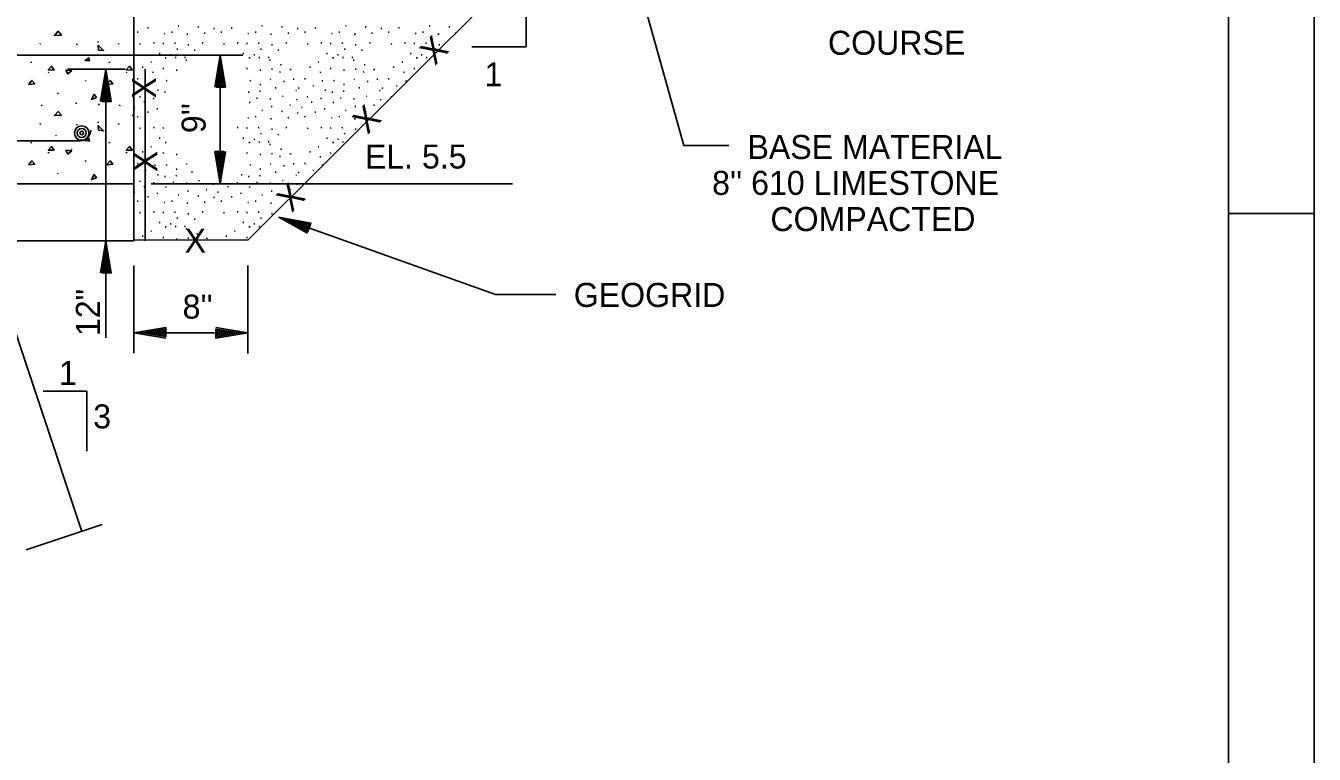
# Model space of a CAD drawing. Extents: x 0 to 320, y -4 to 473.
# Drawn here: x 32.48 to 40, y 10.85 to 15.09 of the extents above; entities that cross this region are included whole.
import ezdxf

# ---------------------------------------------------------------- set-up
doc = ezdxf.new("R2010")
doc.units = 0
for name, color, linetype in [('Level 1', 7, 'Continuous'), ('Level 10', 7, 'Continuous'), ('Level 2', 7, 'Continuous'), ('Level 25', 7, 'Continuous'), ('Level 3', 7, 'Continuous'), ('Level 44', 7, 'Continuous'), ('Level 50', 7, 'Continuous')]:
    doc.layers.add(name, color=color, linetype=linetype)

msp = doc.modelspace()

# ---------------------------------------------------------------- linework, layer by layer
at = {"layer": 'Level 1'}
msp.add_line((39.5, 14), (40, 14), dxfattribs=at)
for points in [[(0, 28), (40, 28), (40, 0), (0, 0)], [(1.5, 27.5), (39.5, 27.5), (39.5, 0.5), (1.5, 0.5)]]:
    msp.add_lwpolyline(points, close=True, dxfattribs=at)
at = {"layer": 'Level 10'}
for p, q in [((32.5694, 14.9868), (32.5711, 14.9913)), ((32.7824, 14.9825), (32.7824, 14.9888)), ((32.9077, 14.996), (32.9077, 15.0018)), ((33.0249, 14.9868), (33.0267, 14.9913)), ((32.5169, 14.8781), (32.5159, 14.8841)), ((32.6614, 14.92), (32.6592, 14.9249)), ((32.9724, 14.8781), (32.9714, 14.8841)), ((32.6184, 14.8192), (32.6153, 14.8244)), ((32.7514, 14.84), (32.751, 14.8446)), ((33.0739, 14.8192), (33.0708, 14.8244)), ((32.833, 14.7704), (32.8358, 14.776)), ((32.6726, 14.6978), (32.673, 14.7029)), ((32.5756, 14.627), (32.5774, 14.6333)), ((32.7785, 14.6394), (32.7777, 14.6441)), ((32.9099, 14.632), (32.9099, 14.6383)), ((33.0311, 14.627), (33.0329, 14.6333)), ((32.5694, 14.5192), (32.5711, 14.5237)), ((32.7824, 14.5149), (32.7824, 14.5212)), ((32.9077, 14.5284), (32.9077, 14.5342)), ((33.0249, 14.5192), (33.0267, 14.5237)), ((32.6614, 14.4524), (32.6592, 14.4573)), ((32.5169, 14.4104), (32.5159, 14.4165)), ((32.6184, 14.3516), (32.6153, 14.3568)), ((32.7514, 14.3724), (32.751, 14.377)), ((32.9724, 14.4104), (32.9714, 14.4165)), ((33.0739, 14.3516), (33.0708, 14.3568)), ((32.833, 14.3028), (32.8358, 14.3084)), ((32.6726, 14.2302), (32.673, 14.2353)), ((32.778, 14.1747), (32.7777, 14.1765))]:
    msp.add_line(p, q, dxfattribs=at)
for points in [[(32.693, 15.0403), (32.6732, 15.0618), (32.652, 15.0381)], [(32.9093, 14.9525), (32.9077, 14.9803), (32.9385, 14.9502)], [(32.8564, 14.889), (32.8311, 14.8922), (32.8524, 14.9065)], [(32.6511, 14.8357), (32.6344, 14.8578), (32.6155, 14.8365)], [(32.753, 14.8333), (32.7308, 14.8135), (32.7189, 14.8357)], [(33.1067, 14.8357), (33.0899, 14.8578), (33.071, 14.8365)], [(32.5003, 14.7517), (32.5209, 14.7754), (32.5375, 14.7558)], [(32.9558, 14.7517), (32.9764, 14.7754), (32.993, 14.7558)], [(32.8963, 14.6758), (32.8679, 14.6647), (32.8829, 14.6954)], [(32.693, 14.5727), (32.6732, 14.5942), (32.652, 14.5704)], [(32.9093, 14.4849), (32.9077, 14.5127), (32.9385, 14.4826)], [(32.8564, 14.4214), (32.8311, 14.4246), (32.8524, 14.4389)], [(32.6511, 14.3681), (32.6344, 14.3902), (32.6155, 14.3689)], [(32.753, 14.3657), (32.7308, 14.3459), (32.7189, 14.3681)], [(33.1067, 14.3681), (33.0899, 14.3902), (33.071, 14.3689)], [(32.5003, 14.2841), (32.5209, 14.3078), (32.5375, 14.2882)], [(32.9558, 14.2841), (32.9764, 14.3078), (32.993, 14.2882)], [(32.8963, 14.2082), (32.8679, 14.1971), (32.8829, 14.2278)]]:
    msp.add_lwpolyline(points, close=True, dxfattribs=at)
msp.add_lwpolyline([(33.1107, 14.5741), (33.1075, 14.5704), (33.1108, 14.5706)], dxfattribs=at)
at = {"layer": 'Level 2'}
for p, q in [((33.1141, 13.8403), (33.1141, 16.1319)), ((32.7275, 14.8403), (33.0645, 14.8403)), ((33.1816, 13.8403), (33.1816, 14.8403)), ((23.4266, 14.4236), (32.8016, 14.4236)), ((33.1141, 14.1736), (28.5308, 14.1736)), ((33.1141, 13.8403), (28.5308, 13.8403))]:
    msp.add_line(p, q, dxfattribs=at)
at = {"layer": 'Level 25'}
for p, q in [((32.8113, 12.1472), (32.2469, 13.8403)), ((32.9308, 12.1871), (32.4863, 12.0389))]:
    msp.add_line(p, q, dxfattribs=at)
at = {"layer": 'Level 3'}
for p, q in [((33.7808, 13.8444), (35.7413, 15.7986)), ((35.4028, 14.9715), (35.4028, 15.321)), ((33.1397, 15.0568), (33.1342, 15.0563)), ((33.2003, 15.0824), (33.1948, 15.0821)), ((33.2964, 15.0487), (33.2913, 15.0496)), ((33.3397, 15.0568), (33.3342, 15.0563)), ((33.3782, 15.0934), (33.3727, 15.0931)), ((33.4308, 15.0446), (33.4241, 15.0446)), ((33.4938, 15.0879), (33.4883, 15.0876)), ((33.5306, 15.0513), (33.5249, 15.0508)), ((33.5847, 15.0779), (33.5798, 15.0784)), ((33.6278, 15.0568), (33.6223, 15.0563)), ((33.6884, 15.0824), (33.6829, 15.0821)), ((33.7846, 15.0487), (33.7794, 15.0496)), ((33.8278, 15.0568), (33.8223, 15.0563)), ((33.8663, 15.0934), (33.8608, 15.0931)), ((33.9189, 15.0446), (33.9122, 15.0446)), ((33.9819, 15.0879), (33.9764, 15.0876)), ((34.0187, 15.0513), (34.0131, 15.0508)), ((34.0728, 15.0779), (34.0679, 15.0784)), ((34.1159, 15.0568), (34.1104, 15.0563)), ((34.1766, 15.0824), (34.1711, 15.0821)), ((34.2727, 15.0487), (34.2676, 15.0496)), ((34.3159, 15.0568), (34.3104, 15.0563)), ((34.3544, 15.0934), (34.3489, 15.0931)), ((34.4071, 15.0446), (34.4003, 15.0446)), ((34.4701, 15.0879), (34.4646, 15.0876)), ((34.5068, 15.0513), (34.5012, 15.0508)), ((34.5609, 15.0779), (34.5561, 15.0784)), ((34.6041, 15.0568), (34.5986, 15.0563)), ((34.6647, 15.0824), (34.6592, 15.0821)), ((34.7608, 15.0487), (34.7557, 15.0496)), ((34.8041, 15.0568), (34.7986, 15.0563)), ((34.8426, 15.0934), (34.8371, 15.0931)), ((34.8952, 15.0446), (34.8884, 15.0446)), ((34.9582, 15.0879), (34.9527, 15.0876)), ((34.9912, 15.051), (34.9893, 15.0508)), ((33.1548, 14.9898), (33.1489, 14.9868)), ((33.2351, 14.9943), (33.2296, 14.9939)), ((33.2902, 14.9907), (33.2847, 14.9902)), ((33.3581, 14.9926), (33.3526, 14.9921)), ((33.3708, 14.9577), (33.3653, 14.9572)), ((33.4351, 14.9833), (33.4296, 14.9829)), ((33.5194, 14.9943), (33.5139, 14.9939)), ((33.6429, 14.9898), (33.6371, 14.9868)), ((33.7232, 14.9943), (33.7177, 14.9939)), ((33.7783, 14.9907), (33.7728, 14.9902)), ((33.8462, 14.9926), (33.8407, 14.9921)), ((33.8589, 14.9577), (33.8534, 14.9572)), ((33.9232, 14.9833), (33.9177, 14.9829)), ((34.0076, 14.9943), (34.0021, 14.9939)), ((34.1311, 14.9898), (34.1252, 14.9868)), ((34.2113, 14.9943), (34.2058, 14.9939)), ((34.2664, 14.9907), (34.2609, 14.9902)), ((34.3343, 14.9926), (34.3288, 14.9921)), ((34.3471, 14.9577), (34.3416, 14.9572)), ((34.4113, 14.9833), (34.4058, 14.9829)), ((34.4957, 14.9943), (34.4902, 14.9939)), ((34.6192, 14.9898), (34.6133, 14.9868)), ((34.6994, 14.9943), (34.6939, 14.9939)), ((34.7546, 14.9907), (34.7491, 14.9902)), ((34.8224, 14.9926), (34.8169, 14.9921)), ((34.8352, 14.9577), (34.8297, 14.9572)), ((34.8994, 14.9833), (34.8939, 14.9829)), ((35.0857, 14.9715), (35.4028, 14.9715)), ((33.7501, 14.9236), (32.2673, 14.9236)), ((33.2187, 14.8818), (33.2132, 14.8813)), ((33.2682, 14.9321), (33.2627, 14.9316)), ((33.3044, 14.9064), (33.2977, 14.9064)), ((33.3324, 14.9246), (33.3269, 14.9242)), ((33.3618, 14.9092), (33.3562, 14.9088)), ((33.4163, 14.9092), (33.4101, 14.9092)), ((33.4241, 14.8946), (33.4186, 14.8942)), ((33.4718, 14.9522), (33.4663, 14.9517)), ((33.6186, 14.1736), (33.6186, 14.9236)), ((33.7563, 14.9321), (33.7508, 14.9316)), ((33.7926, 14.9064), (33.7858, 14.9064)), ((33.8206, 14.9246), (33.8151, 14.9242)), ((33.8499, 14.9092), (33.8443, 14.9088)), ((33.9044, 14.9092), (33.8982, 14.9092)), ((33.9122, 14.8946), (33.9067, 14.8942)), ((33.9599, 14.9522), (33.9544, 14.9517)), ((34.1949, 14.8818), (34.1894, 14.8813)), ((34.2444, 14.9321), (34.2389, 14.9316)), ((34.2807, 14.9064), (34.2739, 14.9064)), ((34.3087, 14.9246), (34.3032, 14.9242)), ((34.3381, 14.9092), (34.3324, 14.9088)), ((34.3926, 14.9092), (34.3863, 14.9092)), ((34.4003, 14.8946), (34.3948, 14.8942)), ((34.4481, 14.9522), (34.4426, 14.9517)), ((34.6831, 14.8818), (34.6776, 14.8813)), ((34.7326, 14.9321), (34.7271, 14.9316)), ((34.7688, 14.9064), (34.7621, 14.9064)), ((34.7968, 14.9246), (34.7913, 14.9242)), ((34.8262, 14.9092), (34.8206, 14.9088)), ((33.1691, 14.8524), (33.1636, 14.8519)), ((33.2296, 14.8231), (33.2241, 14.8226)), ((33.2902, 14.8451), (33.2847, 14.8447)), ((33.3673, 14.8359), (33.3618, 14.8354)), ((33.7783, 14.8451), (33.7728, 14.8447)), ((33.8554, 14.8359), (33.8499, 14.8354)), ((33.9232, 14.8414), (33.9177, 14.8409)), ((33.9709, 14.8248), (33.9654, 14.8244)), ((33.9764, 14.8671), (33.9709, 14.8666)), ((34.0318, 14.8389), (34.0253, 14.8399)), ((34.1453, 14.8524), (34.1398, 14.8519)), ((34.2058, 14.8231), (34.2003, 14.8226)), ((34.2664, 14.8451), (34.2609, 14.8447)), ((34.3436, 14.8359), (34.3381, 14.8354)), ((34.4113, 14.8414), (34.4058, 14.8409)), ((34.4591, 14.8248), (34.4536, 14.8244)), ((34.4646, 14.8671), (34.4591, 14.8666)), ((34.5199, 14.8389), (34.5134, 14.8399)), ((34.6334, 14.8524), (34.6279, 14.8519)), ((34.6939, 14.8231), (34.6884, 14.8226)), ((34.7546, 14.8451), (34.7491, 14.8447)), ((33.1397, 14.7844), (33.1342, 14.7841)), ((33.1874, 14.7442), (33.1818, 14.7438)), ((33.2406, 14.7736), (33.2351, 14.7731)), ((33.3098, 14.7754), (33.3031, 14.7736)), ((33.7979, 14.7754), (33.7912, 14.7736)), ((33.8554, 14.7516), (33.8499, 14.7511)), ((33.9143, 14.7822), (33.9096, 14.7803)), ((33.9453, 14.7332), (33.9398, 14.7327)), ((33.9929, 14.7698), (33.9874, 14.7694)), ((34.0498, 14.7827), (34.0443, 14.7822)), ((34.0784, 14.7292), (34.0728, 14.7326)), ((34.1159, 14.7844), (34.1104, 14.7841)), ((34.1637, 14.7442), (34.1581, 14.7438)), ((34.2168, 14.7736), (34.2113, 14.7731)), ((34.2861, 14.7754), (34.2793, 14.7736)), ((34.3436, 14.7516), (34.3381, 14.7511)), ((34.4024, 14.7822), (34.3977, 14.7803)), ((34.4334, 14.7332), (34.4279, 14.7327)), ((34.4811, 14.7698), (34.4756, 14.7694)), ((34.5379, 14.7827), (34.5324, 14.7822)), ((34.5666, 14.7292), (34.5609, 14.7326)), ((34.6041, 14.7844), (34.5986, 14.7841)), ((34.6518, 14.7442), (34.6462, 14.7438)), ((34.7049, 14.7736), (34.6994, 14.7731)), ((33.1544, 14.6799), (33.1489, 14.6796)), ((33.2333, 14.6707), (33.2278, 14.6703)), ((33.2589, 14.7184), (33.2534, 14.7179)), ((33.2993, 14.7076), (33.2938, 14.7071)), ((33.7874, 14.7076), (33.7819, 14.7071)), ((33.8369, 14.6727), (33.8314, 14.6722)), ((33.8534, 14.7129), (33.8479, 14.7124)), ((33.9141, 14.6689), (33.9084, 14.6684)), ((33.9864, 14.6828), (33.9812, 14.6853)), ((34.0646, 14.7167), (34.0591, 14.7162)), ((34.0701, 14.6634), (34.0646, 14.6629)), ((34.1307, 14.6799), (34.1252, 14.6796)), ((34.2096, 14.6707), (34.2041, 14.6703)), ((34.2352, 14.7184), (34.2297, 14.7179)), ((34.2756, 14.7076), (34.2701, 14.7071)), ((34.3251, 14.6727), (34.3196, 14.6722)), ((34.3416, 14.7129), (34.3361, 14.7124)), ((34.4022, 14.6689), (34.3966, 14.6684)), ((34.4746, 14.6828), (34.4693, 14.6853)), ((34.5527, 14.7167), (34.5472, 14.7162)), ((34.5582, 14.6634), (34.5527, 14.6629)), ((34.6188, 14.6799), (34.6133, 14.6796)), ((33.1213, 14.6176), (33.1158, 14.6171)), ((33.1783, 14.6488), (33.1728, 14.6483)), ((33.2003, 14.5901), (33.1948, 14.5897)), ((33.2553, 14.6102), (33.2498, 14.6098)), ((33.7929, 14.6469), (33.7874, 14.6464)), ((33.8663, 14.6011), (33.8608, 14.6007)), ((33.9214, 14.6231), (33.9159, 14.6226)), ((33.9819, 14.5956), (33.9764, 14.5952)), ((34.0297, 14.6323), (34.0242, 14.6318)), ((34.0728, 14.5856), (34.0679, 14.5861)), ((34.0976, 14.6176), (34.0921, 14.6171)), ((34.1546, 14.6488), (34.1491, 14.6483)), ((34.1766, 14.5901), (34.1711, 14.5897)), ((34.2316, 14.6102), (34.2261, 14.6098)), ((34.2811, 14.6469), (34.2756, 14.6464)), ((34.3544, 14.6011), (34.3489, 14.6007)), ((34.4096, 14.6231), (34.4041, 14.6226)), ((34.4701, 14.5956), (34.4646, 14.5952)), ((34.5178, 14.6323), (34.5123, 14.6318)), ((33.1397, 14.5644), (33.1342, 14.5639)), ((33.4308, 14.5522), (33.4241, 14.5522)), ((33.7846, 14.5563), (33.7794, 14.5572)), ((33.8278, 14.5644), (33.8223, 14.5639)), ((33.9189, 14.5522), (33.9122, 14.5522)), ((34.0187, 14.5589), (34.0131, 14.5584)), ((34.1159, 14.5644), (34.1104, 14.5639)), ((34.2727, 14.5563), (34.2676, 14.5572)), ((34.3159, 14.5644), (34.3104, 14.5639)), ((34.4071, 14.5522), (34.4003, 14.5522)), ((33.1548, 14.4974), (33.1489, 14.4944)), ((33.2351, 14.5019), (33.2296, 14.5016)), ((33.2682, 14.4397), (33.2627, 14.4392)), ((33.2902, 14.4983), (33.2847, 14.4978)), ((33.7232, 14.5019), (33.7177, 14.5016)), ((33.7563, 14.4397), (33.7508, 14.4392)), ((33.7783, 14.4983), (33.7728, 14.4978)), ((33.8206, 14.4322), (33.8151, 14.4318)), ((33.8462, 14.5002), (33.8407, 14.4997)), ((33.8589, 14.4653), (33.8534, 14.4648)), ((33.9232, 14.4909), (33.9177, 14.4906)), ((33.9599, 14.4598), (33.9544, 14.4593)), ((34.0076, 14.5019), (34.0021, 14.5016)), ((34.1311, 14.4974), (34.1252, 14.4944)), ((34.2113, 14.5019), (34.2058, 14.5016)), ((34.2444, 14.4397), (34.2389, 14.4392)), ((34.2664, 14.4983), (34.2609, 14.4978)), ((34.3087, 14.4322), (34.3032, 14.4318)), ((34.3343, 14.5002), (34.3288, 14.4997)), ((34.3471, 14.4653), (34.3416, 14.4648)), ((34.4113, 14.4909), (34.4058, 14.4906)), ((33.1691, 14.3601), (33.1636, 14.3596)), ((33.2187, 14.3894), (33.2132, 14.3889)), ((33.3044, 14.4141), (33.2977, 14.4141)), ((33.7926, 14.4141), (33.7858, 14.4141)), ((33.8499, 14.4168), (33.8443, 14.4164)), ((33.9044, 14.4168), (33.8982, 14.4168)), ((33.9122, 14.4022), (33.9067, 14.4018)), ((33.9764, 14.3747), (33.9709, 14.3742)), ((34.1453, 14.3601), (34.1398, 14.3596)), ((34.1949, 14.3894), (34.1894, 14.3889)), ((34.2807, 14.4141), (34.2739, 14.4141)), ((34.3381, 14.4168), (34.3324, 14.4164)), ((33.1397, 14.2921), (33.1342, 14.2917)), ((33.2296, 14.3307), (33.2241, 14.3302)), ((33.2406, 14.2812), (33.2351, 14.2807)), ((33.2902, 14.3527), (33.2847, 14.3523)), ((33.3098, 14.2831), (33.3031, 14.2812)), ((33.3673, 14.3436), (33.3618, 14.3431)), ((33.4262, 14.2898), (33.4214, 14.2879)), ((33.7783, 14.3527), (33.7728, 14.3523)), ((33.7979, 14.2831), (33.7912, 14.2812)), ((33.8554, 14.3436), (33.8499, 14.3431)), ((33.9143, 14.2898), (33.9096, 14.2879)), ((33.9232, 14.3491), (33.9177, 14.3486)), ((33.9709, 14.3324), (33.9654, 14.3321)), ((34.0318, 14.3466), (34.0253, 14.3476)), ((34.0498, 14.2903), (34.0443, 14.2898)), ((34.1159, 14.2921), (34.1104, 14.2917)), ((34.2058, 14.3307), (34.2003, 14.3302)), ((34.2168, 14.2812), (34.2113, 14.2807)), ((34.2664, 14.3527), (34.2609, 14.3523)), ((33.1874, 14.2518), (33.1818, 14.2514)), ((33.2589, 14.2261), (33.2534, 14.2256)), ((33.2993, 14.2152), (33.2938, 14.2147)), ((33.3653, 14.2206), (33.3598, 14.2201)), ((33.3673, 14.2592), (33.3618, 14.2587)), ((33.4572, 14.2408), (33.4517, 14.2403)), ((33.7471, 14.2261), (33.7416, 14.2256)), ((33.7874, 14.2152), (33.7819, 14.2147)), ((33.8534, 14.2206), (33.8479, 14.2201)), ((33.8554, 14.2592), (33.8499, 14.2587)), ((33.9453, 14.2408), (33.9398, 14.2403)), ((33.9929, 14.2774), (33.9874, 14.2771)), ((34.0646, 14.2243), (34.0591, 14.2238)), ((34.0784, 14.2368), (34.0728, 14.2402)), ((34.1637, 14.2518), (34.1581, 14.2514)), ((33.1544, 14.1876), (33.1489, 14.1872)), ((33.1783, 14.1564), (33.1728, 14.1559)), ((35.3246, 14.1736), (33.2155, 14.1736)), ((33.2333, 14.1783), (33.2278, 14.1779)), ((33.3048, 14.1546), (33.2993, 14.1541)), ((33.3488, 14.1803), (33.3433, 14.1798)), ((33.4259, 14.1766), (33.4203, 14.1761)), ((33.4333, 14.1307), (33.4278, 14.1302)), ((33.4983, 14.1904), (33.4931, 14.1929)), ((33.5416, 14.1399), (33.5361, 14.1394)), ((33.5819, 14.1711), (33.5764, 14.1706)), ((33.6664, 14.1564), (33.6609, 14.1559)), ((33.7214, 14.1783), (33.7159, 14.1779)), ((33.7929, 14.1546), (33.7874, 14.1541)), ((33.8369, 14.1803), (33.8314, 14.1798)), ((33.9141, 14.1766), (33.9084, 14.1761)), ((33.9214, 14.1307), (33.9159, 14.1302)), ((33.9864, 14.1904), (33.9812, 14.1929)), ((34.0297, 14.1399), (34.0242, 14.1394)), ((34.0701, 14.1711), (34.0646, 14.1706)), ((33.1213, 14.1252), (33.1158, 14.1247)), ((33.1397, 14.0721), (33.1342, 14.0716)), ((33.2003, 14.0977), (33.1948, 14.0973)), ((33.2553, 14.1178), (33.2498, 14.1174)), ((33.2964, 14.0639), (33.2913, 14.0648)), ((33.3397, 14.0721), (33.3342, 14.0716)), ((33.3782, 14.1087), (33.3727, 14.1083)), ((33.4308, 14.0598), (33.4241, 14.0598)), ((33.4938, 14.1032), (33.4883, 14.1028)), ((33.5306, 14.0666), (33.5249, 14.0661)), ((33.5847, 14.0932), (33.5798, 14.0937)), ((33.6094, 14.1252), (33.6039, 14.1247)), ((33.6278, 14.0721), (33.6223, 14.0716)), ((33.6884, 14.0977), (33.6829, 14.0973)), ((33.7434, 14.1178), (33.7379, 14.1174)), ((33.7846, 14.0639), (33.7794, 14.0648)), ((33.8278, 14.0721), (33.8223, 14.0716)), ((33.8663, 14.1087), (33.8608, 14.1083)), ((33.9189, 14.0598), (33.9122, 14.0598)), ((33.9819, 14.1032), (33.9764, 14.1028)), ((33.1548, 14.0051), (33.1489, 14.0021)), ((33.2351, 14.0096), (33.2296, 14.0092)), ((33.2902, 14.0059), (33.2847, 14.0054)), ((33.3581, 14.0078), (33.3526, 14.0073)), ((33.4351, 13.9986), (33.4296, 13.9982)), ((33.5194, 14.0096), (33.5139, 14.0092)), ((33.6429, 14.0051), (33.6371, 14.0021)), ((33.7232, 14.0096), (33.7177, 14.0092)), ((33.7783, 14.0059), (33.7728, 14.0054)), ((33.8462, 14.0078), (33.8407, 14.0073)), ((33.9232, 13.9986), (33.9177, 13.9982)), ((33.2682, 13.9473), (33.2627, 13.9468)), ((33.3044, 13.9217), (33.2977, 13.9217)), ((33.3324, 13.9398), (33.3269, 13.9394)), ((33.3618, 13.9244), (33.3562, 13.9241)), ((33.3708, 13.9729), (33.3653, 13.9724)), ((33.4163, 13.9244), (33.4101, 13.9244)), ((33.4241, 13.9098), (33.4186, 13.9094)), ((33.4718, 13.9674), (33.4663, 13.9669)), ((33.7563, 13.9473), (33.7508, 13.9468)), ((33.7926, 13.9217), (33.7858, 13.9217)), ((33.8206, 13.9398), (33.8151, 13.9394)), ((33.8499, 13.9244), (33.8443, 13.9241)), ((33.8589, 13.9729), (33.8534, 13.9724)), ((33.1141, 13.8465), (33.7808, 13.8444)), ((33.1691, 13.8677), (33.1636, 13.8672)), ((33.2187, 13.8971), (33.2132, 13.8966)), ((33.2902, 13.8603), (33.2847, 13.8599)), ((33.3673, 13.8512), (33.3618, 13.8507)), ((33.4351, 13.8567), (33.4296, 13.8562)), ((33.4883, 13.8823), (33.4828, 13.8818)), ((33.5437, 13.8542), (33.5372, 13.8552)), ((33.6572, 13.8677), (33.6517, 13.8672)), ((33.7068, 13.8971), (33.7013, 13.8966)), ((33.7783, 13.8603), (33.7728, 13.8599)), ((33.1141, 13.6974), (33.1141, 13.1855)), ((33.7808, 13.6974), (33.7808, 13.1834)), ((33.7808, 13.3044), (33.1141, 13.3044)), ((32.8405, 12.9646), (32.5852, 12.9646)), ((32.8405, 12.6151), (32.8405, 12.9646))]:
    msp.add_line(p, q, dxfattribs=at)
for points in [[(36.585, 14.3954), (36.3232, 14.3954), (35.9306, 15.7989)], [(35.5761, 13.5283), (35.2251, 13.5283), (33.9615, 13.9779)]]:
    msp.add_lwpolyline(points, dxfattribs=at)
msp.add_arc((32.8016, 14.4861), 0.0625, 270, 0, dxfattribs=at)
at = {"layer": 'Level 44'}
msp.add_line((32.9522, 13.2747), (32.9522, 14.8403), dxfattribs=at)
at = {"layer": 'Level 50'}
for p, q in [((33.6186, 14.9236), (33.6186, 14.9236)), ((32.9522, 14.8403), (32.9522, 14.8403)), ((33.6186, 14.8716), (33.6186, 14.8716)), ((32.9522, 14.7883), (32.9522, 14.7883)), ((33.6186, 14.2256), (33.6186, 14.2256)), ((33.6186, 14.1736), (33.6186, 14.1736)), ((33.9615, 13.9779), (33.9615, 13.9779)), ((34.0105, 13.9605), (34.0105, 13.9605)), ((32.9522, 13.8403), (32.9522, 13.8403)), ((32.9522, 13.7883), (32.9522, 13.7883)), ((33.1141, 13.3044), (33.1141, 13.3044)), ((33.1661, 13.3044), (33.1661, 13.3044)), ((33.7288, 13.3044), (33.7288, 13.3044)), ((33.7808, 13.3044), (33.7808, 13.3044))]:
    msp.add_line(p, q, dxfattribs=at)
for points in [[(33.5876, 14.7366), (33.6186, 14.9236), (33.6496, 14.7366), (33.5966, 14.7366), (33.6186, 14.8716), (33.6396, 14.7446), (33.6056, 14.7446), (33.6186, 14.8216), (33.6296, 14.7526), (33.6156, 14.7526), (33.6186, 14.7696)], [(32.9212, 14.6533), (32.9522, 14.8403), (32.9832, 14.6533), (32.9302, 14.6533), (32.9522, 14.7883), (32.9732, 14.6613), (32.9392, 14.6613), (32.9522, 14.7383), (32.9632, 14.6693), (32.9492, 14.6693), (32.9522, 14.6863)], [(33.6496, 14.3606), (33.6186, 14.1736), (33.5876, 14.3606), (33.6406, 14.3606), (33.6186, 14.2256), (33.5976, 14.3526), (33.6316, 14.3526), (33.6186, 14.2756), (33.6076, 14.3446), (33.6216, 14.3446), (33.6186, 14.3276)], [(34.1273, 13.8861), (33.9615, 13.9779), (34.1481, 13.9445), (34.1303, 13.8945), (34.0105, 13.9605), (34.1372, 13.9377), (34.1258, 13.9057), (34.0576, 13.9438), (34.1263, 13.931), (34.1216, 13.9178), (34.1066, 13.9263)], [(32.9212, 13.6533), (32.9522, 13.8403), (32.9832, 13.6533), (32.9302, 13.6533), (32.9522, 13.7883), (32.9732, 13.6613), (32.9392, 13.6613), (32.9522, 13.7383), (32.9632, 13.6693), (32.9492, 13.6693), (32.9522, 13.6863)], [(33.3011, 13.2734), (33.1141, 13.3044), (33.3011, 13.3354), (33.3011, 13.2824), (33.1661, 13.3044), (33.2931, 13.3254), (33.2931, 13.2914), (33.2161, 13.3044), (33.2851, 13.3154), (33.2851, 13.3014), (33.2681, 13.3044)], [(33.5938, 13.3354), (33.7808, 13.3044), (33.5938, 13.2734), (33.5938, 13.3264), (33.7288, 13.3044), (33.6018, 13.2834), (33.6018, 13.3174), (33.6788, 13.3044), (33.6098, 13.2934), (33.6098, 13.3074), (33.6268, 13.3044)]]:
    msp.add_lwpolyline(points, dxfattribs=at)
for radius in [0.0422, 0.0264, 0.0105]:
    msp.add_circle((32.8111, 14.4688), radius, dxfattribs=at)

# ---------------------------------------------------------------- texts
at = {"layer": 'Level 3'}
for s, p in [('COURSE', (37.1637, 14.925)), ('1', (35.1603, 14.741)), ('BASE MATERIAL', (36.6943, 14.3175)), ('EL. 5.5', (34.4628, 14.262)), ("8'' 610 LIMESTONE", (36.4879, 14.1084)), ('COMPACTED', (36.828, 13.8975)), ("8''", (33.3995, 13.3873)), ('GEOGRID', (35.681, 13.4554)), ('1', (32.6787, 13.001)), ('3', (32.8781, 12.7473))]:
    msp.add_text(s, height=0.14, dxfattribs=at).set_placement(p)
msp.add_text("9''", height=0.14, rotation=90, dxfattribs=at).set_placement((33.5338, 14.4681))
at = {"layer": 'Level 44'}
for s, rotation, p in [('X', 45, (34.8701, 14.8594)), ('X', 90, (33.2452, 14.6699)), ('X', 45, (34.477, 14.4574)), ('X', 90, (33.2523, 14.2404)), ('X', 45, (34.0347, 14.0009)), ('12"', 90, (32.9169, 13.2854))]:
    msp.add_text(s, height=0.14, rotation=rotation, dxfattribs=at).set_placement(p)
msp.add_text('X', height=0.14, dxfattribs=at).set_placement((33.4113, 13.7717))

doc.saveas('drawing.dxf')
